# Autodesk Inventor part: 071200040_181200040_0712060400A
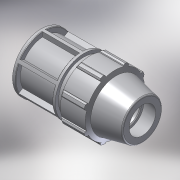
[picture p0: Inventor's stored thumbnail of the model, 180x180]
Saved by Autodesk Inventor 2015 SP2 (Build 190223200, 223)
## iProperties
Created: 2017-02
Part Number: 071200040_181200040_0712060400A
Material: PVC-Piping
Description: PLASSON END PLUG 40
Document SubType Name: Modeling
Designer: KIM
Mass: 92.6774 g
Surface Area: 199.44 cm^2
Volume: 66.1981 cm^3
Density: 1.4 g/cm^3
Appearance: Smooth - White
Author: Кирилл
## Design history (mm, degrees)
derived "07120.ipt"
feature "Solid1::07120.ipt"
tag "TaggingFeature1"
body "Solid1"
other parameters: "d4" = 14.57143, "d5" = 25.5, "d7" = 82, "d8" = 61.5, "d9" = 14.57143, "d11" = 2.91429, "d12" = 65.6, "d13" = 120 deg, "d15" = 12 deg, "d16" = 73.8, "d18" = 2, "d19" = 35 deg, "d20" = 17.5 deg, "d21" = 76.26, "d23" = 0, "d25" = 360 deg, "d27" = 1.64, "d34" = 4.1, "d36" = 0, "d42" = 25.5, "d43" = 2.46, "d46" = 1.2, "d53" = 0.8, "d55" = 360 deg, "d59" = 35.7, "d64" = 102, "d66" = 8.2, "d67" = 4.1, "d68" = 97, "E_" = 82, "H_" = 102, "l_" = 97
